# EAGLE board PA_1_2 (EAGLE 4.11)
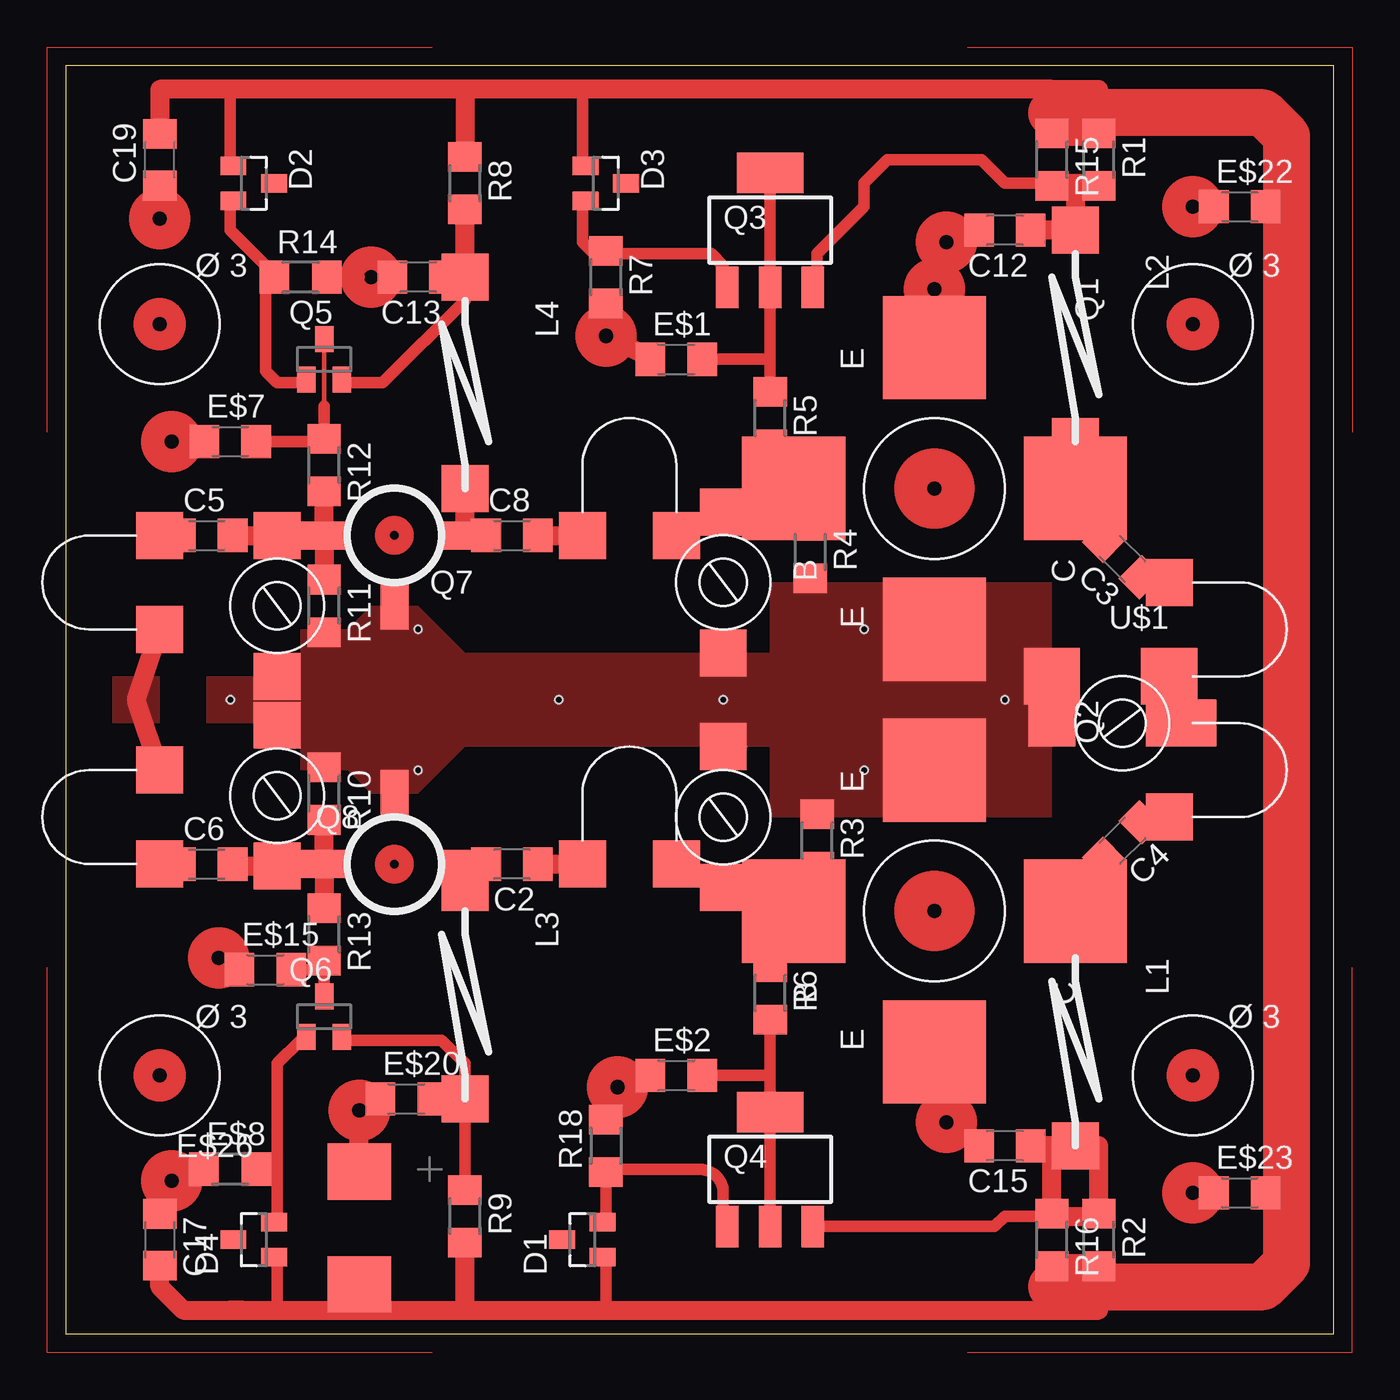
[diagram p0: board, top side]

Size 68.58 x 68.58 mm. Coordinates in mm from the lower left corner, seen from the top.
Outline: 0,0 68.58,0 68.58,68.58 0,68.58 0,0
Copper layers (1*16): Top 0.035mm / dielectric 1.5mm / Bottom 0.035mm
Design rules "default": minimum track width 10mil, minimum drill 10mil, track to track 0mil, track to pad 0mil, pad to pad 0mil, via to via 8mil, smd to smd 0mil, copper to edge 0mil, drill to drill 0mil, minimum pad ring 10mil, minimum via ring 8mil, stop-mask expansion 0mil, vias tented up to drill 0mil, thermal gap 0mil
Holes 0.41 mm at 50.8,34.29 8.89,34.29 19.05,30.48 19.05,38.1 26.67,34.29 35.56,34.29 43.18,38.1 43.18,30.48

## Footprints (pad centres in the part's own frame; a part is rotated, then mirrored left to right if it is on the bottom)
C_AJ = smd 2.54 x 2.54: P$1 3.81,0; P$2 -3.81,0
C1206 = smd 1.6 x 1.8: 1 -1.4,0; 2 1.4,0
SOT23 = smd 1 x 1.4: 1 -0.95,-1.1; 2 0.95,-1.1; 3 0,1.1
R1206 = smd 1.6 x 1.803: 1 -1.422,0; 2 1.422,0
C_EL = smd 3.454 x 3.048: P$1 0,3.048; P$2 0,-3.048
L_1200 = smd 2.54 x 2.54: P$1 -6.35,0; P$2 5.08,0
IND = smd 2.54 x 2.54: P$1 -2.54,0; P$2 2.54,0
SOT122A = smd 5.588 x 5.588: P$B 0,-7.62; P$C 0,7.62; P$E1 -7.62,0; P$E2 7.62,0
SOT223 = smd 1.219 x 2.235: 1 -2.311,-3.099; 2 0,-3.099; 3 2.311,-3.099 | smd 3.6 x 2.2: 4 0,3.099
SOT23C = smd 1 x 1.4: 1 -0.95,-1.1; 2 0.95,-1.1; 3 0,1.1
SOT37 = smd 2.54 x 1.524: B -3.81,0; C 3.81,0 | smd 1.524 x 2.54: E 0,-3.81
COAX = smd 3.048 x 3.048: P$1 0,0; P$2 -6.35,0

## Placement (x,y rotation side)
C1  6 pF  [C_AJ]  35.56,40.64 90 top
C2  [C1206]  24.13,25.4 180 top
C3  [C1206]  57.15,41.91 135 top
C4  [C1206]  57.15,26.67 225 top
C5  [C1206]  7.62,43.18 0 top
C6  [C1206]  7.62,25.4 0 top
C7  6 pF  [C_AJ]  35.56,27.94 90 top
C8  [C1206]  24.13,43.18 0 top
C9  6 pF  [C_AJ]  57.15,33.02 0 top
C10  6 pF  [C_AJ]  11.43,39.37 90 top
C11  6 pF  [C_AJ]  11.43,29.1 90 top
C12  100 pF  [C1206]  50.8,59.69 180 top
C13  100 pF  [C1206]  19.05,57.15 180 top
C15  100 pF  [C1206]  50.8,10.16 180 top
C17  100 nF  [C1206]  5.08,5.08 270 top
C19  100 nF  [C1206]  5.08,63.5 90 top
D1  [SOT23]  27.94,5.08 90 top
D2  [SOT23]  10.16,62.23 270 top
D3  [SOT23]  29.21,62.23 270 top
D4  [SOT23]  10.16,5.08 90 top
E$1  [C1206]  33.02,52.7 0 top
E$2  [C1206]  33.02,13.97 0 top
E$3  [VIS_3]  60.96,54.61 0 top
E$4  [VIS_3]  60.96,13.97 0 top
E$5  [VIS_3]  5.08,13.97 0 top
E$6  [VIS_3]  5.08,54.61 0 top
E$7  [C1206]  8.89,48.26 0 top
E$8  [R1206]  8.89,8.89 0 top
E$9  [PASTILLE_3]  5.71,8.26 0 top
E$10  [PASTILLE_3]  5.08,60.33 0 top
E$11  [PASTILLE_3]  16.51,57.15 0 top
E$12  [PASTILLE_3]  29.21,53.98 0 top
E$13  [PASTILLE_3]  46.99,56.52 0 top
E$14  [PASTILLE_3]  47.62,59.05 0 top
E$15  [C1206]  10.79,19.68 0 top
E$16  [PASTILLE_3]  5.71,48.26 0 top
E$17  [PASTILLE_3]  29.84,13.34 0 top
E$18  [PASTILLE_3]  8.26,20.32 0 top
E$19  [PASTILLE_3]  47.62,11.43 0 top
E$20  [C1206]  18.41,12.7 0 top
E$21  [PASTILLE_3]  15.88,12.06 0 top
E$22  [C1206]  63.5,60.96 0 top
E$23  [C1206]  63.5,7.62 0 top
E$24  [PASTILLE_3]  60.96,60.96 0 top
E$25  [PASTILLE_3]  60.96,7.62 0 top
E$26  [C_EL]  15.88,5.71 0 top
L1  [L_1200]  54.61,15.24 270 top
L2  [L_1200]  54.61,53.34 270 top
L3  [L_1200]  21.59,17.78 270 top
L4  [L_1200]  21.59,50.8 270 top
L5  [IND]  30.48,43.18 0 top
L6  [IND]  30.48,25.4 0 top
L7  [IND]  5.08,40.64 90 top
L8  [IND]  5.08,27.94 90 top
L10  [IND]  59.69,38.1 270 top
L11  [IND]  59.69,30.48 270 top
Q1  BFQ34  [SOT122A]  46.99,45.72 270 top
Q2  BFQ34  [SOT122A]  46.99,22.86 270 top
Q3  [SOT223]  38.1,59.69 0 top
Q4  [SOT223]  38.1,8.89 0 top
Q5  PMBT2907A  [SOT23C]  13.97,52.7 0 top
Q6  PMBT2907A  [SOT23C]  13.97,17.14 0 top
Q7  BFR96  [SOT37]  17.78,43.18 0 top
Q8  BFR96R  [SOT37]  17.78,25.4 180 top
R1  12  [R1206]  55.88,63.5 270 top
R2  [R1206]  55.88,5.08 270 top
R3  [R1206]  40.64,26.67 270 top
R4  [R1206]  40.27,42.28 270 top
R5  [R1206]  38.1,49.53 270 top
R6  [R1206]  38.1,18.41 270 top
R7  4.7 k  [R1206]  29.21,57.15 270 top
R8  [R1206]  21.59,62.23 270 top
R9  [R1206]  21.59,6.35 270 top
R10  [R1206]  13.97,29.21 270 top
R11  [R1206]  13.97,39.37 270 top
R12  [R1206]  13.97,46.99 270 top
R13  [R1206]  13.97,21.59 270 top
R14  10 k  [R1206]  12.7,57.15 0 top
R15  6.8  [R1206]  53.34,63.5 270 top
R16  [R1206]  53.34,5.08 270 top
R18  [R1206]  29.21,10.16 90 top
U$1  COAX  [COAX]  53.34,35.56 180 top

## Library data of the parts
C1-C13 C15 C17 C19 D1-D4 E$1-E$26 L1-L8 L10 L11 Q1-Q8 R1-R16 R18 U$1 = _mylib

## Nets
N$1: Q4.2
N$2: C3.2 L2.P$2 Q1.P$C
N$3: C9.P$1 L10.P$2 L11.P$1 U$1.P$2
N$4: C7.P$2 L6.P$2 Q2.P$B R3.2 R6.1
N$5: Q1.P$E2
N$6: C4.2 L1.P$1 Q2.P$C
N$7: Q3.2 R5.1
N$8: Q4.3 R2.1 R16.1
N$9: Q3.1 R7.1
N$10: C12.1 L2.P$1 R1.2 R15.2
N$12: D2.1 D3.1 R1.1 R2.2 R8.1 R9.2 R15.1 R16.2
N$13: L7.P$1 L8.P$2
N$14: C1.P$1 Q1.P$B R4.1 R5.2
N$15: C8.1 L4.P$2 Q7.C
N$16: C6.2 C11.P$2 Q8.C R10.2 R13.1
N$18: C5.2 C10.P$1 Q7.B R11.1 R12.2
N$20: D2.2
N$21: C6.1 L8.P$1
N$23: C5.1 L7.P$2
N$24: C8.2 L5.P$1
N$25: C2.1 L6.P$1
N$26: L4.P$1 R8.2
N$30: C2.2 L3.P$1 Q8.B
N$31: C4.1 L11.P$2
N$32: C3.1 L10.P$1
S$6: R7.2
S$10: Q4.1
S$16: R4.2
S$17: C7.P$1
S$19: L3.P$2 R9.1

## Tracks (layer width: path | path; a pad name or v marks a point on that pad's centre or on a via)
N$1
  Top 0.61: 38.1,13.97 34.29,13.97 | Q4.2 38.1,13.97 | 38.1,13.97 38.1,17.14
N$2
  Top 0.61: Q1.P$C L2.P$2
  Top 1.016: C3.2 55.88,44.45 Q1.P$C
N$3
  Top 1.016: L11.P$1 C9.P$1 | C9.P$1 L10.P$2 C9.P$1
N$4
  Top 1.016: Q2.P$B R3.2 | R6.1 Q2.P$B | Q2.P$B C7.P$2 L6.P$2
N$5
  Top 0.127: 49.53,35.56 48.26,36.83 46.99,35.56
  Top 0.406: 48.26,36.83 Q1.P$E2
N$6
  Top 1.016: C4.2 54.61,24.13 Q2.P$C L1.P$1
N$7
  Top 0.61: 38.1,50.8 R5.1 38.1,52.7 | 38.1,54.61 Q3.2 | 38.1,52.7 38.1,54.61 | 38.1,54.61 38.1,62.23 | 34.29,52.7 38.1,52.7
N$8
  Top 0.61: 53.34,6.35 50.8,6.35 50.24,5.79 Q4.3
  Top 1.016: 53.34,10.16 R16.1 53.34,6.35 55.88,6.35 R2.1 55.88,10.16 52.07,10.16
N$9
  Top 0.61: Q3.1 35.79,56.92 arc90 35.56,57.15 35.56,57.78 34.92,58.42 29.21,58.42 | R7.1 29.21,58.42 | 27.94,60.96 27.94,59.05 28.57,58.42 29.21,58.42
N$10
  Top 0.61: R15.2 53.34,62.23 50.8,62.23 49.53,63.5 44.45,63.5 43.18,62.23 43.18,60.96 40.64,58.42 40.64,57.15
  Top 1.016: R1.2 55.96,62.16 55.88,62.23 54.61,62.23 | 53.34,62.23 54.61,62.23 | C12.1 L2.P$1 54.61,62.23
N$11
  Top 0.61: 29.21,6.35 29.21,8.89 34.29,8.89 arc-90 35.56,7.62 35.56,5.08
N$12
  Top 0.61: D2.1 8.89,63.18 8.89,67.31 | D3.1 27.94,63.18 27.94,67.31 | 29.38,1.44 29.21,1.27 29.21,3.81 | 11.43,1.27 11.43,3.81 | 8.89,1.27 9.06,1.44
  Top 1.016: 5.08,64.77 5.08,67.31 8.89,67.31 21.59,67.31 | 21.59,63.5 R8.1 21.59,67.31 | 21.59,67.31 27.94,67.31 53.34,67.31 | 53.34,67.31 55.88,67.31 R1.1 55.88,64.77 53.34,64.77 R15.1 53.34,66.04 53.34,67.31 | R2.2 55.88,1.27 53.34,1.27 | R16.2 53.34,2.54 53.34,1.27 | 53.34,1.27 29.21,1.27 21.59,1.27 | 21.59,1.27 R9.2 | 15.88,1.27 11.43,1.27 9.53,1.27 | 21.59,1.27 16.51,1.27 15.88,1.27 | 9.53,1.27 8.89,1.27 | 5.08,3.81 5.08,2.54 6.35,1.27 9.53,1.27 | 15.88,1.27 15.88,2.54
  Top 2.54: 53.34,66.04 64.77,66.04 66.04,64.77 66.04,3.81 64.77,2.54 53.34,2.54
N$13
  Top 1.016: L7.P$1 3.81,34.29 L8.P$2
N$14
  Top 0.61: Q1.P$B 38.1,48.26 38.1,46.99 | Q1.P$B R4.1 | C1.P$1 Q1.P$B
  Top 1.016: 38.1,48.26 R5.2 | 33.02,43.18 arc-16 C1.P$1
N$15
  Top 1.016: 22.86,43.18 C8.1 Q7.C L4.P$2
N$16
  Top 1.016: C6.2 8.89,25.4 8.89,25.29 C11.P$2 13.97,25.29 | 13.97,25.29 Q8.C | 13.97,22.86 R13.1 13.97,25.29 | 13.97,25.29 R10.2
N$18
  Top 1.016: C5.2 C10.P$1 | C10.P$1 Q7.B | 13.97,40.64 R11.1 Q7.B | 13.97,45.72 R12.2 Q7.B | C5.2 8.89,43.18 | C5.2 C10.P$1
N$20
  Top 0.61: D2.2 arc90 8.89,61.11
N$21
  Top 0.61: 6.35,25.4 C6.1 L8.P$1
N$23
  Top 1.016: 6.35,43.18 C5.1 L7.P$2
N$24
  Top 1.016: 25.4,43.18 C8.2 L5.P$1
N$25
  Top 1.016: C2.1 L6.P$1
N$26
  Top 0.61: 15.24,51.44 17.14,51.44 21.59,55.88 L4.P$1 21.59,56.52
  Top 1.016: 21.59,60.96 R8.2 L4.P$1
N$29
  Top 0.051: 19.81,-1.02 -1.02,-1.02 -1.02,19.81
N$30
  Top 1.016: C2.2 Q8.B L3.P$1
N$31
  Top 1.016: C4.1 L11.P$2
N$32
  Top 1.016: C3.1 L10.P$1
N$33
  Top 0.051: 48.77,-1.02 69.6,-1.02 69.6,19.81
N$34
  Top 0.051: 19.81,69.6 -1.02,69.6 -1.02,48.77
N$35
  Top 0.051: 69.6,48.77 69.6,69.6 48.77,69.6
S$1
  Top 0.61: 8.89,60.96 8.89,59.69 10.79,57.78 10.79,52.07 11.43,51.44 12.7,51.44
S$2
  Top 0.61: 13.97,57.15 15.88,57.15
S$3
  Top 0.254: 13.97,50.16 13.97,53.34
  Top 0.61: 10.16,48.26 13.97,48.26 13.97,50.16
S$4
  Top 1.016: 31.75,52.7 30.48,53.34
S$5
  Top 1.016: 15.88,8.89 15.88,10.79
S$6
  Top 1.016: 29.21,55.88 R7.2 29.21,55.24
S$7
  pour Top: 7.62,35.56 7.62,33.02 13.34,33.02 13.34,35.56
S$8
  Top 0.61: 13.97,18.41 13.97,19.68 12.06,19.68
S$9
  Top 0.61: 11.43,6.35 11.43,8.89 | 11.43,8.89 10.16,8.89 | 11.43,8.89 11.43,14.61 12.7,15.88
S$10
  Top 0.61: Q4.1 35.79,6.12
S$11
  Top 1.016: 53.34,3.81 55.88,3.81
S$12
  Top 0.61: 6.35,8.89 7.62,8.89
S$14
  pour Top: 11.43,36.83 12.7,36.83 12.7,38.1 15.24,38.1 16.51,39.37 19.05,39.37 21.59,36.83 38.1,36.83 38.1,40.64 53.34,40.64 53.34,27.94 38.1,27.94 38.1,31.75 21.59,31.75 19.05,29.21 16.51,29.21 15.24,30.48 12.7,30.48 12.7,31.75 11.43,31.75
S$15
  pour Top: 2.54,35.56 2.54,33.02 5.08,33.02 5.08,35.56
  pour Top: 7.62,35.56 7.62,33.02 10.16,33.02 11.43,33.02 11.43,35.56
S$16
  Top 1.016: 40.64,40.64 40.27,40.64 R4.2
S$17
  Top 0.127: C7.P$1 36.83,31.75
S$19
  Top 0.61: 15.24,15.88 20.32,15.88 21.59,14.61 L3.P$2 R9.1 21.59,7.62
S$21
  Top 0.127: 46.99,31.75 48.26,30.48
